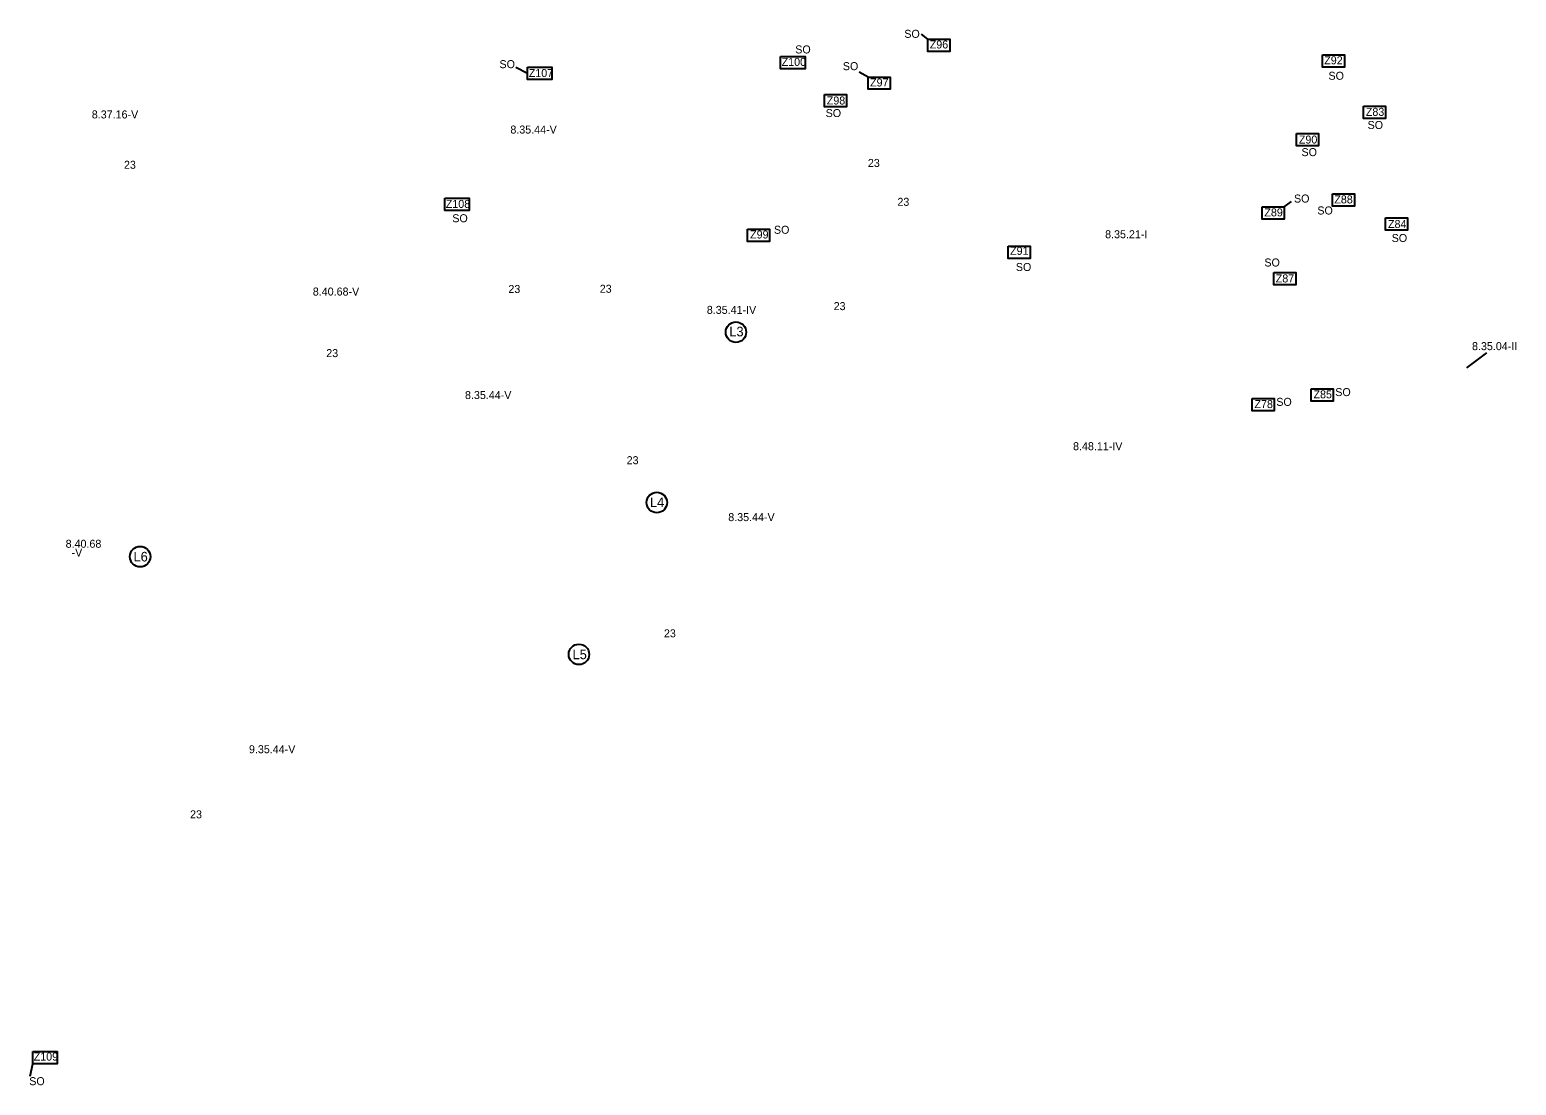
# Model space of a CAD drawing. Extents: x -450307 to -440553, y -1134449 to -1129789.
# Drawn here: x -443186 to -441328, y -1133443 to -1132124 of the extents above; entities that cross this region are included whole.
import ezdxf

# ---------------------------------------------------------------- set-up
doc = ezdxf.new("R2010")
doc.units = 0
for name, color, linetype in [('01_PARC_VNEJSI', 7, 'Continuous'), ('19_PAR_CIS_STAV', 7, 'Continuous'), ('Vrstva 18', 7, 'Continuous'), ('Vrstva 28', 7, 'Continuous'), ('Vrstva 36', 7, 'Continuous')]:
    doc.layers.add(name, color=color, linetype=linetype)

msp = doc.modelspace()

# ---------------------------------------------------------------- linework, layer by layer
at = {"layer": '19_PAR_CIS_STAV'}
msp.add_lwpolyline([(-441657.9, -1132584.5), (-441630.5, -1132584.5), (-441630.5, -1132599.9), (-441657.9, -1132599.9)], close=True, dxfattribs=at)
at = {"layer": 'Vrstva 18'}
for p, q in [((-442063.4, -1132135.7), (-442071.1, -1132129.3)), ((-442563.8, -1132178.3), (-442578.2, -1132171.1)), ((-442137.9, -1132182.9), (-442149.2, -1132176.8)), ((-441618.1, -1132344.9), (-441608.8, -1132338.2)), ((-443185.2, -1133431), (-443181.9, -1133415.9))]:
    msp.add_line(p, q, dxfattribs=at)
for points in [[(-442063.4, -1132135.7), (-442036, -1132135.7), (-442036, -1132151.1), (-442063.4, -1132151.1)], [(-442247.5, -1132157.2), (-442216.7, -1132157.2), (-442216.7, -1132172.6), (-442247.5, -1132172.6)], [(-441570, -1132155.3), (-441542.6, -1132155.3), (-441542.6, -1132170.7), (-441570, -1132170.7)], [(-442563.8, -1132170.6), (-442533.1, -1132170.6), (-442533.1, -1132186), (-442563.8, -1132186)], [(-442137.9, -1132182.9), (-442110.5, -1132182.9), (-442110.5, -1132198.2), (-442137.9, -1132198.2)], [(-442192.5, -1132204.9), (-442165.1, -1132204.9), (-442165.1, -1132220.3), (-442192.5, -1132220.3)], [(-441518.9, -1132219.3), (-441491.5, -1132219.3), (-441491.5, -1132234.7), (-441518.9, -1132234.7)], [(-441602.6, -1132253.6), (-441575.2, -1132253.6), (-441575.2, -1132269), (-441602.6, -1132269)], [(-441557.5, -1132329), (-441530.2, -1132329), (-441530.2, -1132344.4), (-441557.5, -1132344.4)], [(-442667.1, -1132334.4), (-442636.3, -1132334.4), (-442636.3, -1132349.8), (-442667.1, -1132349.8)], [(-441645.5, -1132344.9), (-441618.1, -1132344.9), (-441618.1, -1132360.3), (-441645.5, -1132360.3)], [(-441491.3, -1132358.9), (-441463.9, -1132358.9), (-441463.9, -1132374.3), (-441491.3, -1132374.3)], [(-442288.6, -1132372.9), (-442261.2, -1132372.9), (-442261.2, -1132388.3), (-442288.6, -1132388.3)], [(-441962.9, -1132394.1), (-441935.5, -1132394.1), (-441935.5, -1132409.5), (-441962.9, -1132409.5)], [(-441630.7, -1132427.3), (-441603.4, -1132427.3), (-441603.4, -1132442.7), (-441630.7, -1132442.7)], [(-441584.1, -1132572.3), (-441556.7, -1132572.3), (-441556.7, -1132587.7), (-441584.1, -1132587.7)], [(-443181.9, -1133400.5), (-443151.2, -1133400.5), (-443151.2, -1133415.9), (-443181.9, -1133415.9)]]:
    msp.add_lwpolyline(points, close=True, dxfattribs=at)
at = {"layer": 'Vrstva 28'}
msp.add_line((-441389.5, -1132546), (-441364.5, -1132527.6), dxfattribs=at)
at = {"layer": 'Vrstva 36'}
for centre in [(-442303.1, -1132501.7), (-442402, -1132714.5), (-443047.7, -1132782.1), (-442499.3, -1132904.2)]:
    msp.add_circle(centre, 12.8, dxfattribs=at)

# ---------------------------------------------------------------- texts
at = {"layer": '01_PARC_VNEJSI'}
msp.add_text('SO', height=10, dxfattribs=at).set_placement((-441627.8, -1132593.7))
at = {"layer": '19_PAR_CIS_STAV'}
msp.add_text('Z78', height=10, dxfattribs=at).set_placement((-441655.1, -1132596.5))
at = {"layer": 'Vrstva 18'}
for s, p in [('SO', (-442092.7, -1132133.9)), ('SO', (-442229, -1132153.4)), ('Z96', (-442060.9, -1132147.2)), ('SO', (-442598.6, -1132171.8)), ('Z100', (-442246, -1132169)), ('SO', (-442169.5, -1132174.3)), ('Z92', (-441567.9, -1132167)), ('Z107', (-442562, -1132182.9)), ('Z97', (-442135.5, -1132194.7)), ('SO', (-441562.6, -1132186.3)), ('Z98', (-442189.6, -1132217.2)), ('Z83', (-441515.9, -1132231.4)), ('SO', (-442191, -1132232.9)), ('SO', (-441513.7, -1132247.8)), ('Z90', (-441599.6, -1132266)), ('SO', (-441596.3, -1132281.7)), ('SO', (-441605.7, -1132339.7)), ('Z88', (-441555.3, -1132340.8)), ('Z108', (-442665.7, -1132346.4)), ('Z89', (-441642.7, -1132357)), ('SO', (-441576.5, -1132354.6)), ('SO', (-442657.6, -1132364.3)), ('SO', (-442255.6, -1132378.7)), ('Z84', (-441488.2, -1132371.5)), ('Z99', (-442285.4, -1132384.6)), ('SO', (-441483.6, -1132389)), ('Z91', (-441960.5, -1132405)), ('SO', (-441953.3, -1132425.2)), ('SO', (-441642.7, -1132419.6)), ('Z87', (-441628.5, -1132439.5)), ('Z85', (-441581.3, -1132584.3)), ('SO', (-441554.1, -1132581.5)), ('Z109', (-443180.7, -1133411.7)), ('SO', (-443186.3, -1133442.4))]:
    msp.add_text(s, height=10, dxfattribs=at).set_placement(p)
at = {"layer": 'Vrstva 28'}
for s, p in [('8.37.16-V', (-443108.1, -1132234.6)), ('8.35.44-V', (-442585, -1132253.5)), ('23', (-443067.9, -1132297.5)), ('23', (-442138.2, -1132295.2)), ('23', (-442101.3, -1132343.8)), ('8.35.21-I', (-441841.7, -1132384.3)), ('23', (-442587.5, -1132452.7)), ('23', (-442473.3, -1132452.4)), ('8.40.68-V', (-442831.9, -1132455.9)), ('23', (-442181, -1132474.1)), ('8.35.41-IV', (-442339.5, -1132478.8)), ('8.35.04-II', (-441383.2, -1132524.1)), ('23', (-442815.1, -1132532.8)), ('8.35.44-V', (-442641.7, -1132585.2)), ('8.48.11-IV', (-441881.8, -1132649.1)), ('23', (-442439.7, -1132666.6)), ('8.35.44-V', (-442312.7, -1132737.7)), ('8.40.68', (-443140.8, -1132771)), ('  -V', (-443140.8, -1132782)), ('23', (-442393.1, -1132882.9)), ('9.35.44-V', (-442911.7, -1133027.7)), ('23', (-442985.3, -1133109))]:
    msp.add_text(s, height=10, dxfattribs=at).set_placement(p)
at = {"layer": 'Vrstva 36'}
for s, p in [('L3', (-442311.4, -1132506.9)), ('L4', (-442410.6, -1132720.2)), ('L6', (-443056, -1132788.1)), ('L5', (-442507.3, -1132910.2))]:
    msp.add_text(s, height=12, dxfattribs=at).set_placement(p)

doc.saveas('drawing.dxf')
